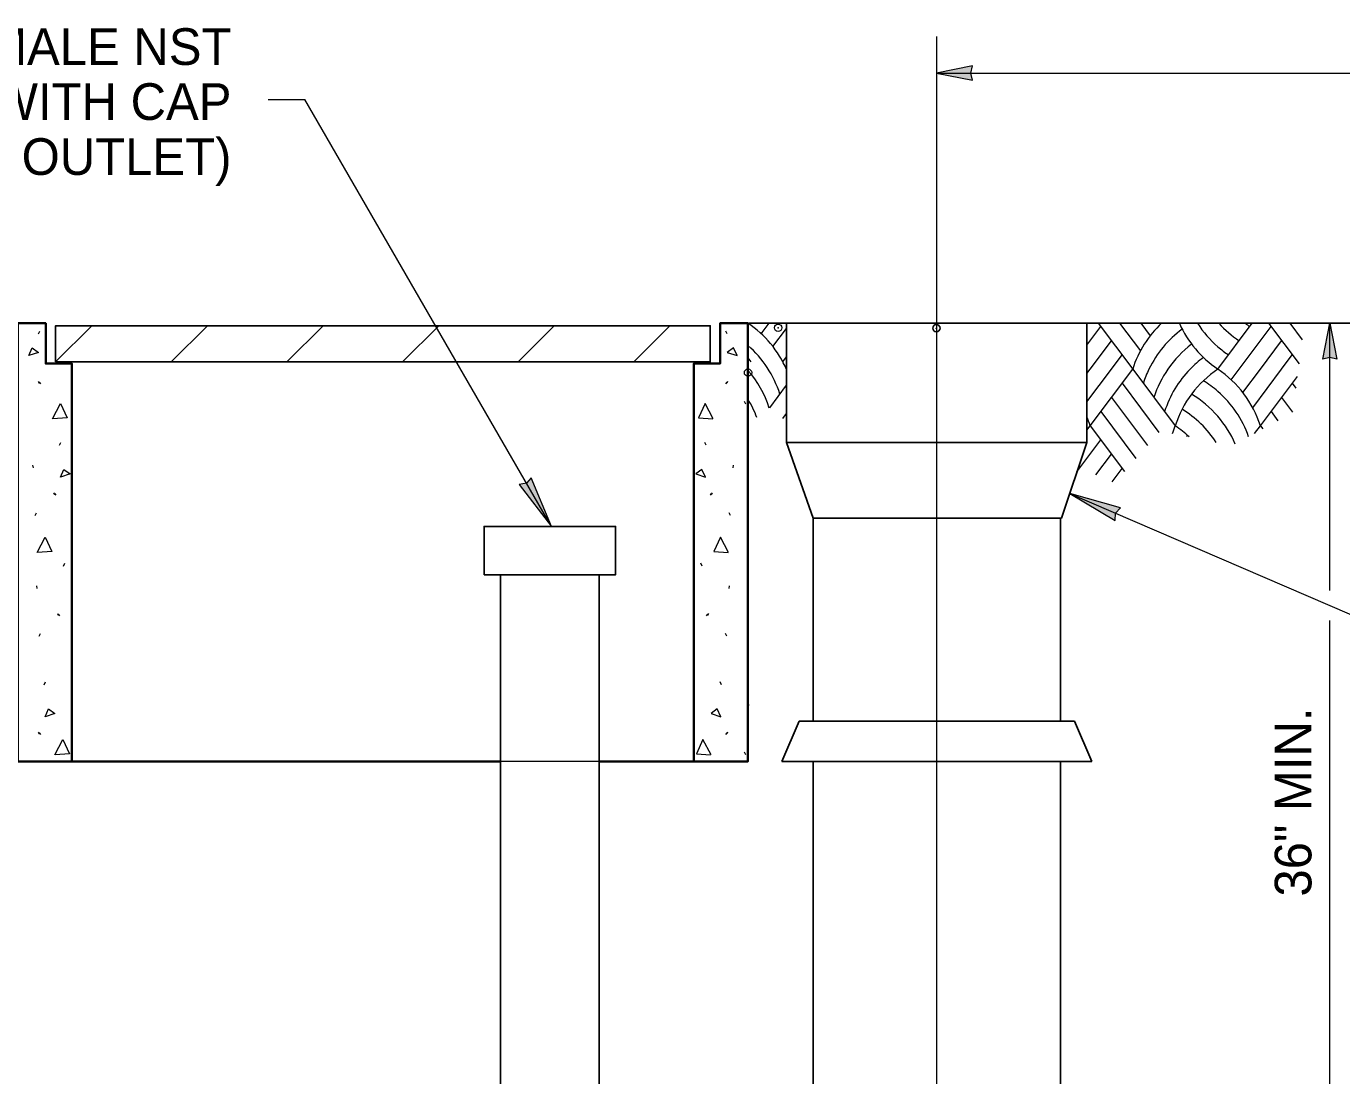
# Model space of a CAD drawing. Extents: x 99860 to 103153, y 99998 to 102077.
# Drawn here: x 100386 to 100960, y 100610 to 101068 of the extents above; entities that cross this region are included whole.
import ezdxf
from ezdxf.enums import TextEntityAlignment as Align

# ---------------------------------------------------------------- set-up
doc = ezdxf.new("R2010")
doc.units = 0
doc.header["$LTSCALE"] = 6.4
doc.header["$PDMODE"] = 32
doc.header["$PDSIZE"] = 3.2
for name, color, linetype, lineweight in [('1', 7, 'Continuous', 13), ('10', 7, 'Continuous', 13), ('13', 7, 'Continuous', 13), ('15', 7, 'Continuous', 13), ('17', 7, 'Continuous', 35), ('18', 7, 'Continuous', 25), ('20', 7, 'Continuous', 13), ('6', 7, 'Continuous', 25)]:
    doc.layers.add(name, color=color, linetype=linetype, lineweight=lineweight)
doc.layers.add('3', color=7, linetype='Continuous')

msp = doc.modelspace()

# ---------------------------------------------------------------- hatches: boundary and pattern name
at = {"layer": '13'}
msp.add_hatch(color=256, dxfattribs=at).paths.add_polyline_path([(100841.387, 100864.193), (100861.168, 100852.412), (100861.38, 100855.571), (100863.533, 100857.894)])
at = {"layer": '15'}
for points in [[(100783.251, 101047.641), (100798.976, 101044.557), (100798.248, 101047.641), (100798.976, 101050.725)], [(100954.839, 100938.462), (100957.923, 100922.737), (100954.839, 100923.465), (100951.755, 100922.737)], [(100615.3, 100849.812), (100606.47, 100871.075), (100604.413, 100868.668), (100601.3, 100868.09)]]:
    msp.add_hatch(color=256, dxfattribs=at).paths.add_polyline_path(points)

# ---------------------------------------------------------------- linework, layer by layer
at = {"layer": '1'}
for p, q in [((100391.615, 100933.787), (100392.178, 100935.05)), ((100692.012, 100933.787), (100691.449, 100935.05)), ((100391.438, 100913.037), (100391.851, 100912.312)), ((100391.851, 100912.75), (100392.426, 100912.062)), ((100691.776, 100912.75), (100691.201, 100912.062)), ((100692.188, 100913.037), (100691.776, 100912.312)), ((100700.138, 100903.212), (100699.576, 100904.35)), ((100400.826, 100885.187), (100401.388, 100886.45)), ((100682.801, 100885.187), (100682.238, 100886.45)), ((100389.038, 100876.537), (100389.201, 100875.4)), ((100694.588, 100876.537), (100694.426, 100875.4)), ((100398.138, 100864.437), (100398.551, 100863.712)), ((100398.551, 100864.15), (100399.113, 100863.462)), ((100685.076, 100864.15), (100684.513, 100863.462)), ((100685.488, 100864.437), (100685.076, 100863.712)), ((100390.176, 100854.625), (100390.751, 100855.75)), ((100693.451, 100854.625), (100692.876, 100855.75)), ((100402.488, 100832.512), (100403.063, 100833.775)), ((100681.138, 100832.512), (100680.563, 100833.775)), ((100390.713, 100823.862), (100390.876, 100822.725)), ((100692.913, 100823.862), (100692.751, 100822.725)), ((100399.813, 100811.762), (100400.226, 100811.037)), ((100400.226, 100811.487), (100400.788, 100810.787)), ((100683.401, 100811.487), (100682.838, 100810.787)), ((100683.813, 100811.762), (100683.401, 100811.037)), ((100391.851, 100801.95), (100392.426, 100803.087)), ((100691.776, 100801.95), (100691.201, 100803.087)), ((100394.126, 100780.7), (100394.688, 100781.962)), ((100689.501, 100780.7), (100688.938, 100781.962)), ((100701.276, 100772.05), (100701.126, 100770.912)), ((100391.438, 100759.95), (100391.851, 100759.225)), ((100391.851, 100759.662), (100392.426, 100758.975)), ((100691.776, 100759.662), (100691.201, 100758.975)), ((100692.188, 100759.95), (100691.776, 100759.225)), ((100700.138, 100750.125), (100699.576, 100751.262))]:
    msp.add_line(p, q, dxfattribs=at)
at = {"layer": '1', "lineweight": 25}
msp.add_lwpolyline([(100399.051, 100921.6), (100399.051, 100937.387), (100684.576, 100937.387), (100684.576, 100921.6)], close=True, dxfattribs=at)
at = {"layer": '1'}
for points in [[(100387.35, 100924.348), (100388.9, 100927.748), (100391.587, 100925.761)], [(100696.277, 100924.348), (100694.727, 100927.748), (100692.039, 100925.761)], [(100401.138, 100871.262), (100402.688, 100874.675), (100405.363, 100872.687)], [(100682.488, 100871.262), (100680.938, 100874.675), (100678.263, 100872.687)], [(100394.438, 100766.775), (100395.988, 100770.175), (100398.676, 100768.187)], [(100689.188, 100766.775), (100687.638, 100770.175), (100684.951, 100768.187)]]:
    msp.add_lwpolyline(points, close=True, dxfattribs=at)
for points in [[(100397.688, 100896.712), (100401.263, 100903.375), (100404.101, 100897.125), (100397.851, 100896.712)], [(100685.938, 100896.712), (100682.363, 100903.375), (100679.526, 100897.125), (100685.776, 100896.712)], [(100391.001, 100838.487), (100394.563, 100845.15), (100397.413, 100838.887), (100391.163, 100838.487)], [(100692.626, 100838.487), (100689.063, 100845.15), (100686.213, 100838.887), (100692.463, 100838.487)], [(100398.675, 100750.125), (100402.25, 100756.787), (100405.088, 100750.537), (100398.838, 100750.125)], [(100684.952, 100750.125), (100681.377, 100756.787), (100678.539, 100750.537), (100684.789, 100750.125)]]:
    msp.add_lwpolyline(points, dxfattribs=at)
at = {"layer": '10'}
for p in [(100714.201, 100936.5), (100701.088, 100916.925)]:
    msp.add_point(p, dxfattribs=at)
at = {"layer": '13'}
for p, q in [((100848.876, 100928.907), (100854.958, 100937.017)), ((100853.874, 100938.462), (100868.879, 100918.455)), ((100863.155, 100938.462), (100872.222, 100926.372)), ((100872.436, 100938.462), (100876.527, 100933.008)), ((100906.004, 100918.455), (100921.009, 100938.462)), ((100915.285, 100918.455), (100929.206, 100937.017)), ((100928.122, 100938.462), (100941.45, 100920.691)), ((100937.402, 100938.462), (100942.851, 100931.198)), ((100850.318, 100918.455), (100859.599, 100930.83)), ((100924.565, 100918.455), (100933.846, 100930.83)), ((100859.599, 100918.455), (100864.239, 100924.643)), ((100933.846, 100918.455), (100938.486, 100924.643)), ((100848.876, 100916.531), (100850.318, 100918.454)), ((100848.876, 100904.157), (100859.599, 100918.454)), ((100850.318, 100893.705), (100868.879, 100918.454)), ((100868.879, 100918.454), (100887.441, 100893.705)), ((100911.821, 100913.837), (100915.285, 100918.454)), ((100916.918, 100908.258), (100924.565, 100918.454)), ((100921.222, 100901.622), (100933.846, 100918.454)), ((100924.565, 100893.705), (100940.725, 100915.251)), ((100864.239, 100912.267), (100880.32, 100890.825)), ((100938.486, 100912.267), (100940.049, 100910.183)), ((100859.599, 100906.08), (100875.296, 100885.15)), ((100933.846, 100906.08), (100938.648, 100899.677)), ((100854.958, 100899.893), (100870.272, 100879.474)), ((100929.206, 100899.893), (100932.164, 100895.948)), ((100848.876, 100891.783), (100850.318, 100893.705)), ((100850.318, 100893.705), (100865.248, 100873.799)), ((100922.071, 100890.379), (100924.565, 100893.705)), ((100924.565, 100893.705), (100925.6, 100892.326)), ((100844.572, 100873.67), (100854.958, 100887.518)), ((100852.842, 100872.322), (100859.599, 100881.331)), ((100859.854, 100869.298), (100864.239, 100875.144)), ((100841.387, 100864.193), (101030.057, 100782.829))]:
    msp.add_line(p, q, dxfattribs=at)
msp.add_lwpolyline([(100841.387, 100864.193), (100861.168, 100852.412), (100861.38, 100855.571), (100863.533, 100857.894)], close=True, dxfattribs=at)
for centre, start, end in [((100913.642, 100904.219), 133.19502, 162.3566), ((100932.203, 100957.441), 203.83104, 236.09639), ((100936.844, 100963.628), 212.39562, 228.95992), ((100941.485, 100969.815), 221.87314, 236.09639), ((100946.126, 100976.002), 233.05424, 236.09639), ((100918.282, 100898.031), 126.30626, 154.22661), ((100922.922, 100891.844), 127.1006, 145.49109), ((100936.845, 100963.628), 228.95986, 236.09639), ((100927.563, 100885.657), 126.331, 135.71278), ((100918.282, 100898.03), 154.22654, 162.3566), ((100922.922, 100891.843), 145.49102, 162.3566), ((100927.563, 100885.656), 135.71269, 162.3566), ((100932.203, 100879.469), 123.90361, 162.3566), ((100875.161, 100873.281), 48.95968, 58.54646), ((100879.803, 100879.469), 17.6434, 56.09634), ((100870.521, 100867.094), 40.94134, 59.30215), ((100875.163, 100873.281), 19.46416, 48.95974), ((100805.556, 100879.469), 17.6434, 22.74071), ((100865.881, 100860.907), 33.00314, 58.48736), ((100870.522, 100867.094), 23.37175, 40.94141), ((100842.679, 100907.942), 337.94432, 342.3566), ((100861.24, 100854.72), 46.58948, 56.09639), ((100847.319, 100901.755), 344.29333, 345.01126)]:
    msp.add_arc(centre, 46.972, start, end, dxfattribs=at)
at = {"layer": '15'}
for p, q in [((100783.251, 101063.641), (100783.251, 100327.05)), ((100783.251, 101047.641), (101637.901, 101047.641)), ((100491.768, 101036.063), (100507.769, 101036.063)), ((100615.3, 100849.812), (100507.769, 101036.063)), ((100954.839, 100821.801), (100954.839, 100938.462)), ((100954.839, 100520.562), (100954.839, 100808.733))]:
    msp.add_line(p, q, dxfattribs=at)
at = {"layer": '15', "lineweight": 25}
for p, q in [((100701.476, 100938.462), (100717.926, 100938.462)), ((100848.876, 100938.462), (101864.101, 100938.462))]:
    msp.add_line(p, q, dxfattribs=at)
at = {"layer": '15'}
for points in [[(100783.251, 101047.641), (100798.976, 101044.557), (100798.248, 101047.641), (100798.976, 101050.725)], [(100954.839, 100938.462), (100957.923, 100922.737), (100954.839, 100923.465), (100951.755, 100922.737)], [(100615.3, 100849.812), (100606.47, 100871.075), (100604.413, 100868.668), (100601.3, 100868.09)]]:
    msp.add_lwpolyline(points, close=True, dxfattribs=at)
at = {"layer": '17', "lineweight": 13}
for p, q in [((100399.051, 100921.6), (100414.838, 100937.387)), ((100449.476, 100921.6), (100465.276, 100937.387)), ((100499.938, 100921.6), (100515.726, 100937.387)), ((100550.401, 100921.6), (100566.188, 100937.387)), ((100600.801, 100921.6), (100616.588, 100937.387)), ((100651.263, 100921.6), (100667.051, 100937.387)), ((100636.163, 100747.25), (100593.126, 100747.25))]:
    msp.add_line(p, q, dxfattribs=at)
at = {"layer": '17'}
for p, q in [((100406.188, 100747.25), (100593.126, 100747.25)), ((100636.163, 100747.25), (100677.413, 100747.25))]:
    msp.add_line(p, q, dxfattribs=at)
for points in [[(100382.538, 100938.462), (100394.726, 100938.462), (100394.726, 100920.862), (100406.188, 100920.862), (100406.188, 100747.25), (100382.538, 100747.25)], [(100701.063, 100938.462), (100688.901, 100938.462), (100688.901, 100920.862), (100677.413, 100920.862), (100677.413, 100747.25), (100701.063, 100747.25)]]:
    msp.add_lwpolyline(points, close=True, dxfattribs=at)
at = {"layer": '18'}
for p, q in [((100717.926, 100938.462), (100848.876, 100938.462)), ((100717.926, 100886.475), (100717.926, 100938.462)), ((100848.876, 100886.475), (100848.876, 100938.462)), ((100717.926, 100886.475), (100848.876, 100886.475)), ((100729.451, 100853.412), (100717.926, 100886.475)), ((100837.763, 100853.412), (100848.876, 100886.475)), ((100729.451, 100853.412), (100837.763, 100853.412)), ((100729.451, 100764.812), (100729.451, 100853.412)), ((100837.376, 100764.812), (100837.376, 100853.412)), ((100715.776, 100747.25), (100723.326, 100764.812)), ((100723.326, 100764.812), (100843.476, 100764.812)), ((100851.026, 100747.25), (100843.476, 100764.812)), ((100715.776, 100747.25), (100851.026, 100747.25)), ((100729.451, 100747.25), (100729.451, 100567.2)), ((100837.376, 100747.25), (100837.376, 100567.2))]:
    msp.add_line(p, q, dxfattribs=at)
at = {"layer": '20'}
for p, q in [((100706.88, 100933.845), (100710.344, 100938.462)), ((100711.977, 100928.266), (100717.926, 100936.198)), ((100702.405, 100921.631), (100701.088, 100923.387)), ((100716.281, 100921.631), (100717.926, 100923.823)), ((100710.546, 100901.609), (100717.926, 100911.449)), ((100716.284, 100896.886), (100717.926, 100899.075))]:
    msp.add_line(p, q, dxfattribs=at)
for centre, start, end in [((100674.862, 100899.477), 56.0955, 56.09634), ((100674.862, 100899.477), 23.53699, 56.0955), ((100727.265, 100899.477), 123.90361, 123.9045), ((100670.223, 100893.29), 48.95968, 48.96107), ((100670.222, 100893.29), 17.6434, 48.95911), ((100665.582, 100887.102), 40.94134, 40.9433), ((100665.581, 100887.102), 17.75976, 40.94104), ((100660.942, 100880.915), 31.33163, 31.33464), ((100660.941, 100880.915), 20.4015, 31.33172)]:
    msp.add_arc(centre, 46.972, start, end, dxfattribs=at)
at = {"layer": '3'}
msp.add_point((100783.251, 100936.312), dxfattribs=at)
at = {"layer": '6'}
for p, q in [((100593.126, 100436.937), (100593.126, 100828.687)), ((100636.163, 100436.937), (100636.163, 100828.687))]:
    msp.add_line(p, q, dxfattribs=at)
msp.add_lwpolyline([(100585.926, 100828.687), (100643.338, 100828.687), (100643.338, 100849.812), (100585.926, 100849.812)], close=True, dxfattribs=at)

# ---------------------------------------------------------------- texts
at = {"layer": '20'}
for s, p in [('2" FEMALE × IP × 2 1/2" MALE NST', (100475.77, 101051.199)), ('HOSE CONNECTION WITH CAP', (100475.77, 101027.199)), ('(BLOWOFF OUTLET)', (100475.769, 101003.199))]:
    msp.add_text(s, height=16, dxfattribs=at).set_placement(p, align=Align.RIGHT)
msp.add_text('36" MIN.', height=16, rotation=90, dxfattribs=at).set_placement((100946.839, 100729.514), align=Align.CENTER)

doc.saveas('drawing.dxf')
